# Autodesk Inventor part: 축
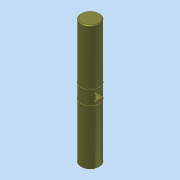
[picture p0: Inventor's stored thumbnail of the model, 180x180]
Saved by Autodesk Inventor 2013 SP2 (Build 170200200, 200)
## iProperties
Company: 한국ATC센터
Created: 2015-04
Part Number: 축
Document SubType Name: Modeling
Designer: KYOUNG IL JANG
Density: 7.85 g/cm^3
Material: 강
Author: KYOUNG IL JANG
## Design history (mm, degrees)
sketch "스케치1"
  geometry: C1 r 11 at (0, 0); 1 further point
  constraints: 1 centre point, 1 coincident
  dimensions: "d0" = 22 diameter of C1
extrude "돌출1" new body sketch "스케치1" stored distance "d1" = 150; taper "d2" = 0 deg
sketch "스케치2"
  geometry: L1 (-10.247, -4)-(10.247, -4); L2 (-10.247, 4)-(10.247, 4); A1 r 11 centre (0, 0) between (-10.247, -4) and (10.247, -4) reference; 1 further point
  constraints: 4 end point, 4 point on circle, 2 parallel, 1 horizontal
  dimensions: "d3" = 8 distance between parallel lines of L2 L1
extrude "돌출2" cut sketch "스케치2" stored distance "d4" = 8; taper "d5" = 0 deg
sketch "스케치3"
  geometry: 5 further points
hole "구멍1" sketch "스케치3" at (-4, 4), (4, 4), (4, -4), (-4, -4) diameter "d6" = 2; stored, may be unused: countersink angle "d10" = 90 deg, drill point angle "d12" = 118 deg; dims "d7" = 6, "d8" = 4, "d9" = 2, "d11" = 8
chamfer "모따기1" distance "d13" = 1; stored, may be unused: second distance "d14" = 2, angle "d15" = 45 deg
sketch "스케치4"
  geometry: L1 (-10, 9)-(-11, 9); L2 (-11, 9)-(-11, 7.8); L3 (-11, 7.8)-(-10, 7.8); L4 (-10, 7.8)-(-10, 9); L5 (-10, 75)-(10, 75) reference; L6 (0, -10)-(0, 60) reference; 1 further point
  constraints: 8 end point, 2 parallel, 1 horizontal, 1 perpendicular
  dimensions: "d16" = 7.8 distance from line of L3 point (0, 0); "d17" = 67.2 distance between parallel lines of L3 L5 (derived); "d18" = 11 distance from line of point (0, 0) L2; "d19" = 1 distance of L2.end L3.end; "d20" = 1.2 distance of L1.end L2.end
revolve "회전1" sketch "스케치4" stored, may be unused: angle "d21" = 90 deg
node "솔리드1"
mirror "대칭1"
mirror "대칭2"
